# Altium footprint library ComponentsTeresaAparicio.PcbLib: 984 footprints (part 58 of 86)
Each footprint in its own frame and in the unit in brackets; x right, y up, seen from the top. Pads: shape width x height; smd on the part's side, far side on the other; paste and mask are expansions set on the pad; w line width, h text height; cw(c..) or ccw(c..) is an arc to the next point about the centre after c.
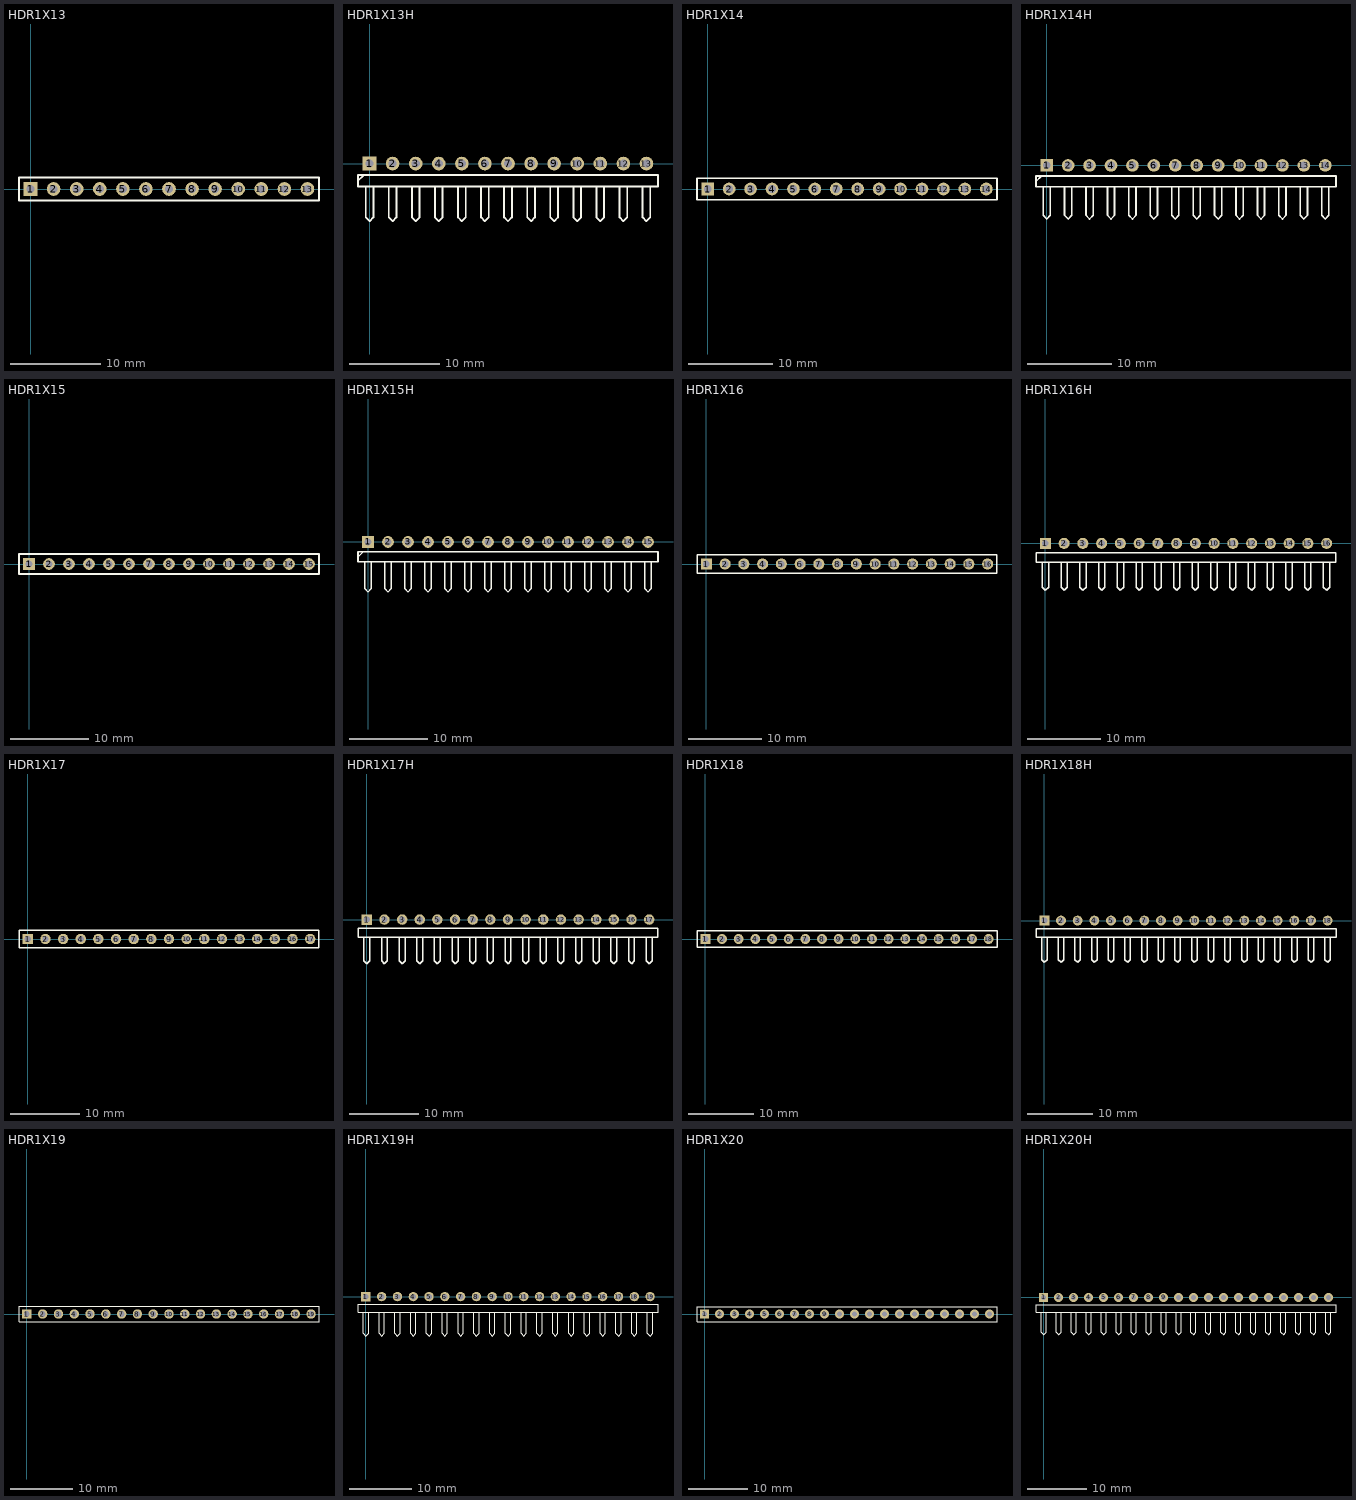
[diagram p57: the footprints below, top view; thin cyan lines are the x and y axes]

## HDR1X13 [mm] "Connector; Header; 13 Position"
pads (13):
  rect 1.5x1.5 hole 0.9: 1(0,0)
  round 1.5 hole 0.9: 2(2.54,0) 3(5.08,0) 4(7.62,0) 5(10.16,0) 6(12.7,0) 7(15.24,0) 8(17.78,0) 9(20.32,0) 10(22.86,0) 11(25.4,0) 12(27.94,0) 13(30.48,0)
Top Overlay:
  lines w0.2: -1.27,-1.27 -1.27,1.27 0.635,1.27 31.75,1.27 31.75,-1.27 -1.27,-1.27

## HDR1X13H [mm] "Connector; Header; 13 Position; Right Angle"
pads (13):
  rect 1.5x1.5 hole 0.9: 1(0,0)
  round 1.5 hole 0.9: 2(2.54,0) 3(5.08,0) 4(7.62,0) 5(10.16,0) 6(12.7,0) 7(15.24,0) 8(17.78,0) 9(20.32,0) 10(22.86,0) 11(25.4,0) 12(27.94,0) 13(30.48,0)
Top Overlay:
  lines w0.2: -1.27,-1.905 -0.635,-1.27 ; -0.423,-2.54 -0.423,-5.927 0,-6.35 0.423,-5.927 0.423,-2.54 ; 2.117,-2.54 2.117,-5.927 2.54,-6.35 2.963,-5.927 2.963,-2.54 ; 4.657,-2.54 4.657,-5.927 5.08,-6.35 5.503,-5.927 5.503,-2.54 ; 7.197,-2.54 7.197,-5.927 7.62,-6.35 8.043,-5.927 8.043,-2.54 ; 9.737,-2.54 9.737,-5.927 10.16,-6.35 10.583,-5.927 10.583,-2.54 ; 12.277,-2.54 12.277,-5.927 12.7,-6.35 13.123,-5.927 13.123,-2.54 ; 14.817,-2.54 14.817,-5.927 15.24,-6.35 15.663,-5.927 15.663,-2.54 ; 17.357,-2.54 17.357,-5.927 17.78,-6.35 18.203,-5.927 18.203,-2.54 ; 19.897,-2.54 19.897,-5.927 20.32,-6.35 20.743,-5.927 20.743,-2.54 ; 22.437,-2.54 22.437,-5.927 22.86,-6.35 23.283,-5.927 23.283,-2.54 ; 24.977,-2.54 24.977,-5.927 25.4,-6.35 25.823,-5.927 25.823,-2.54 ; 27.517,-2.54 27.517,-5.927 27.94,-6.35 28.363,-5.927 28.363,-2.54 ; 30.057,-2.54 30.057,-5.927 30.48,-6.35 30.903,-5.927 30.903,-2.54 ; -1.27,-2.54 31.75,-2.54 31.75,-1.27 0.635,-1.27 -1.27,-1.27 -1.27,-2.54

## HDR1X14 [mm] "Connector; Header; 14 Position"
pads (14):
  rect 1.5x1.5 hole 0.9: 1(0,0)
  round 1.5 hole 0.9: 2(2.54,0) 3(5.08,0) 4(7.62,0) 5(10.16,0) 6(12.7,0) 7(15.24,0) 8(17.78,0) 9(20.32,0) 10(22.86,0) 11(25.4,0) 12(27.94,0) 13(30.48,0) 14(33.02,0)
Top Overlay:
  lines w0.2: -1.27,-1.27 34.29,-1.27 34.29,1.27 0.635,1.27 -1.27,1.27 -1.27,-1.27

## HDR1X14H [mm] "Connector; Header; 14 Position; Right Angle"
pads (14):
  rect 1.5x1.5 hole 0.9: 1(0,0)
  round 1.5 hole 0.9: 2(2.54,0) 3(5.08,0) 4(7.62,0) 5(10.16,0) 6(12.7,0) 7(15.24,0) 8(17.78,0) 9(20.32,0) 10(22.86,0) 11(25.4,0) 12(27.94,0) 13(30.48,0) 14(33.02,0)
Top Overlay:
  lines w0.2: -1.27,-1.905 -0.635,-1.27 ; -0.423,-2.54 -0.423,-5.927 0,-6.35 0.423,-5.927 0.423,-2.54 ; 2.117,-2.54 2.117,-5.927 2.54,-6.35 2.963,-5.927 2.963,-2.54 ; 4.657,-2.54 4.657,-5.927 5.08,-6.35 5.503,-5.927 5.503,-2.54 ; 7.197,-2.54 7.197,-5.927 7.62,-6.35 8.043,-5.927 8.043,-2.54 ; 9.737,-2.54 9.737,-5.927 10.16,-6.35 10.583,-5.927 10.583,-2.54 ; 12.277,-2.54 12.277,-5.927 12.7,-6.35 13.123,-5.927 13.123,-2.54 ; 14.817,-2.54 14.817,-5.927 15.24,-6.35 15.663,-5.927 15.663,-2.54 ; 17.357,-2.54 17.357,-5.927 17.78,-6.35 18.203,-5.927 18.203,-2.54 ; 19.897,-2.54 19.897,-5.927 20.32,-6.35 20.743,-5.927 20.743,-2.54 ; 22.437,-2.54 22.437,-5.927 22.86,-6.35 23.283,-5.927 23.283,-2.54 ; 24.977,-2.54 24.977,-5.927 25.4,-6.35 25.823,-5.927 25.823,-2.54 ; 27.517,-2.54 27.517,-5.927 27.94,-6.35 28.363,-5.927 28.363,-2.54 ; 30.057,-2.54 30.057,-5.927 30.48,-6.35 30.903,-5.927 30.903,-2.54 ; 32.597,-2.54 32.597,-5.927 33.02,-6.35 33.443,-5.927 33.443,-2.54 ; -1.27,-2.54 -1.27,-1.27 0.635,-1.27 34.29,-1.27 34.29,-2.54 -1.27,-2.54

## HDR1X15 [mm] "Connector; Header; 15 Position"
pads (15):
  rect 1.5x1.5 hole 0.9: 1(0,0)
  round 1.5 hole 0.9: 2(2.54,0) 3(5.08,0) 4(7.62,0) 5(10.16,0) 6(12.7,0) 7(15.24,0) 8(17.78,0) 9(20.32,0) 10(22.86,0) 11(25.4,0) 12(27.94,0) 13(30.48,0) 14(33.02,0) 15(35.56,0)
Top Overlay:
  lines w0.2: -1.27,-1.27 -1.27,1.27 0.635,1.27 36.83,1.27 36.83,-1.27 -1.27,-1.27

## HDR1X15H [mm] "Connector; Header; 15 Position; Right Angle"
pads (15):
  rect 1.5x1.5 hole 0.9: 1(0,0)
  round 1.5 hole 0.9: 2(2.54,0) 3(5.08,0) 4(7.62,0) 5(10.16,0) 6(12.7,0) 7(15.24,0) 8(17.78,0) 9(20.32,0) 10(22.86,0) 11(25.4,0) 12(27.94,0) 13(30.48,0) 14(33.02,0) 15(35.56,0)
Top Overlay:
  lines w0.2: -1.27,-1.905 -0.635,-1.27 ; -0.423,-2.54 -0.423,-5.927 0,-6.35 0.423,-5.927 0.423,-2.54 ; 2.117,-2.54 2.117,-5.927 2.54,-6.35 2.963,-5.927 2.963,-2.54 ; 4.657,-2.54 4.657,-5.927 5.08,-6.35 5.503,-5.927 5.503,-2.54 ; 7.197,-2.54 7.197,-5.927 7.62,-6.35 8.043,-5.927 8.043,-2.54 ; 9.737,-2.54 9.737,-5.927 10.16,-6.35 10.583,-5.927 10.583,-2.54 ; 12.277,-2.54 12.277,-5.927 12.7,-6.35 13.123,-5.927 13.123,-2.54 ; 14.817,-2.54 14.817,-5.927 15.24,-6.35 15.663,-5.927 15.663,-2.54 ; 17.357,-2.54 17.357,-5.927 17.78,-6.35 18.203,-5.927 18.203,-2.54 ; 19.897,-2.54 19.897,-5.927 20.32,-6.35 20.743,-5.927 20.743,-2.54 ; 22.437,-2.54 22.437,-5.927 22.86,-6.35 23.283,-5.927 23.283,-2.54 ; 24.977,-2.54 24.977,-5.927 25.4,-6.35 25.823,-5.927 25.823,-2.54 ; 27.517,-2.54 27.517,-5.927 27.94,-6.35 28.363,-5.927 28.363,-2.54 ; 30.057,-2.54 30.057,-5.927 30.48,-6.35 30.903,-5.927 30.903,-2.54 ; 32.597,-2.54 32.597,-5.927 33.02,-6.35 33.443,-5.927 33.443,-2.54 ; 35.137,-2.54 35.137,-5.927 35.56,-6.35 35.983,-5.927 35.983,-2.54 ; -1.27,-2.54 -1.27,-1.27 0.635,-1.27 36.83,-1.27 36.83,-2.54 -1.27,-2.54

## HDR1X16 [mm] "Connector; Header; 16 Position"
pads (16):
  rect 1.5x1.5 hole 0.9: 1(0,0)
  round 1.5 hole 0.9: 2(2.54,0) 3(5.08,0) 4(7.62,0) 5(10.16,0) 6(12.7,0) 7(15.24,0) 8(17.78,0) 9(20.32,0) 10(22.86,0) 11(25.4,0) 12(27.94,0) 13(30.48,0) 14(33.02,0) 15(35.56,0) 16(38.1,0)
Top Overlay:
  lines w0.2: -1.27,-1.27 -1.27,1.27 0.635,1.27 39.37,1.27 39.37,-1.27 -1.27,-1.27

## HDR1X16H [mm] "Connector; Header; 16 Position; Right Angle"
pads (16):
  rect 1.5x1.5 hole 0.9: 1(0,0)
  round 1.5 hole 0.9: 2(2.54,0) 3(5.08,0) 4(7.62,0) 5(10.16,0) 6(12.7,0) 7(15.24,0) 8(17.78,0) 9(20.32,0) 10(22.86,0) 11(25.4,0) 12(27.94,0) 13(30.48,0) 14(33.02,0) 15(35.56,0) 16(38.1,0)
Top Overlay:
  lines w0.2: -0.423,-2.54 -0.423,-5.927 0,-6.35 0.423,-5.927 0.423,-2.54 ; 2.117,-2.54 2.117,-5.927 2.54,-6.35 2.963,-5.927 2.963,-2.54 ; 4.657,-2.54 4.657,-5.927 5.08,-6.35 5.503,-5.927 5.503,-2.54 ; 7.197,-2.54 7.197,-5.927 7.62,-6.35 8.043,-5.927 8.043,-2.54 ; 9.737,-2.54 9.737,-5.927 10.16,-6.35 10.583,-5.927 10.583,-2.54 ; 12.277,-2.54 12.277,-5.927 12.7,-6.35 13.123,-5.927 13.123,-2.54 ; 14.817,-2.54 14.817,-5.927 15.24,-6.35 15.663,-5.927 15.663,-2.54 ; 17.357,-2.54 17.357,-5.927 17.78,-6.35 18.203,-5.927 18.203,-2.54 ; 19.897,-2.54 19.897,-5.927 20.32,-6.35 20.743,-5.927 20.743,-2.54 ; 22.437,-2.54 22.437,-5.927 22.86,-6.35 23.283,-5.927 23.283,-2.54 ; 24.977,-2.54 24.977,-5.927 25.4,-6.35 25.823,-5.927 25.823,-2.54 ; 27.517,-2.54 27.517,-5.927 27.94,-6.35 28.363,-5.927 28.363,-2.54 ; 30.057,-2.54 30.057,-5.927 30.48,-6.35 30.903,-5.927 30.903,-2.54 ; 32.597,-2.54 32.597,-5.927 33.02,-6.35 33.443,-5.927 33.443,-2.54 ; 35.137,-2.54 35.137,-5.927 35.56,-6.35 35.983,-5.927 35.983,-2.54 ; 37.677,-2.54 37.677,-5.927 38.1,-6.35 38.523,-5.927 38.523,-2.54 ; -1.27,-2.54 39.37,-2.54 39.37,-1.27 0.635,-1.27 -1.27,-1.27 -1.27,-2.54

## HDR1X17 [mm] "Connector; Header; 17 Position"
pads (17):
  rect 1.5x1.5 hole 0.9: 1(0,0)
  round 1.5 hole 0.9: 2(2.54,0) 3(5.08,0) 4(7.62,0) 5(10.16,0) 6(12.7,0) 7(15.24,0) 8(17.78,0) 9(20.32,0) 10(22.86,0) 11(25.4,0) 12(27.94,0) 13(30.48,0) 14(33.02,0) 15(35.56,0) 16(38.1,0) 17(40.64,0)
Top Overlay:
  lines w0.2: -1.27,-1.27 41.91,-1.27 41.91,1.27 0.635,1.27 -1.27,1.27 -1.27,-1.27

## HDR1X17H [mm] "Connector; Header; 17 Position; Right Angle"
pads (17):
  rect 1.5x1.5 hole 0.9: 1(0,0)
  round 1.5 hole 0.9: 2(2.54,0) 3(5.08,0) 4(7.62,0) 5(10.16,0) 6(12.7,0) 7(15.24,0) 8(17.78,0) 9(20.32,0) 10(22.86,0) 11(25.4,0) 12(27.94,0) 13(30.48,0) 14(33.02,0) 15(35.56,0) 16(38.1,0) 17(40.64,0)
Top Overlay:
  lines w0.2: -0.423,-2.54 -0.423,-5.927 0,-6.35 0.423,-5.927 0.423,-2.54 ; 2.117,-2.54 2.117,-5.927 2.54,-6.35 2.963,-5.927 2.963,-2.54 ; 4.657,-2.54 4.657,-5.927 5.08,-6.35 5.503,-5.927 5.503,-2.54 ; 7.197,-2.54 7.197,-5.927 7.62,-6.35 8.043,-5.927 8.043,-2.54 ; 9.737,-2.54 9.737,-5.927 10.16,-6.35 10.583,-5.927 10.583,-2.54 ; 12.277,-2.54 12.277,-5.927 12.7,-6.35 13.123,-5.927 13.123,-2.54 ; 14.817,-2.54 14.817,-5.927 15.24,-6.35 15.663,-5.927 15.663,-2.54 ; 17.357,-2.54 17.357,-5.927 17.78,-6.35 18.203,-5.927 18.203,-2.54 ; 19.897,-2.54 19.897,-5.927 20.32,-6.35 20.743,-5.927 20.743,-2.54 ; 22.437,-2.54 22.437,-5.927 22.86,-6.35 23.283,-5.927 23.283,-2.54 ; 24.977,-2.54 24.977,-5.927 25.4,-6.35 25.823,-5.927 25.823,-2.54 ; 27.517,-2.54 27.517,-5.927 27.94,-6.35 28.363,-5.927 28.363,-2.54 ; 30.057,-2.54 30.057,-5.927 30.48,-6.35 30.903,-5.927 30.903,-2.54 ; 32.597,-2.54 32.597,-5.927 33.02,-6.35 33.443,-5.927 33.443,-2.54 ; 35.137,-2.54 35.137,-5.927 35.56,-6.35 35.983,-5.927 35.983,-2.54 ; 37.677,-2.54 37.677,-5.927 38.1,-6.35 38.523,-5.927 38.523,-2.54 ; 40.217,-2.54 40.217,-5.927 40.64,-6.35 41.063,-5.927 41.063,-2.54 ; -1.27,-2.54 41.91,-2.54 41.91,-1.27 0.635,-1.27 -1.27,-1.27 -1.27,-2.54

## HDR1X18 [mm] "Connector; Header; 18 Position"
pads (18):
  rect 1.5x1.5 hole 0.9: 1(0,0)
  round 1.5 hole 0.9: 2(2.54,0) 3(5.08,0) 4(7.62,0) 5(10.16,0) 6(12.7,0) 7(15.24,0) 8(17.78,0) 9(20.32,0) 10(22.86,0) 11(25.4,0) 12(27.94,0) 13(30.48,0) 14(33.02,0) 15(35.56,0) 16(38.1,0) 17(40.64,0) 18(43.18,0)
Top Overlay:
  lines w0.2: -1.27,-1.27 44.45,-1.27 44.45,1.27 0.635,1.27 -1.27,1.27 -1.27,-1.27

## HDR1X18H [mm] "Connector; Header; 18 Position; Right Angle"
pads (18):
  rect 1.5x1.5 hole 0.9: 1(0,0)
  round 1.5 hole 0.9: 2(2.54,0) 3(5.08,0) 4(7.62,0) 5(10.16,0) 6(12.7,0) 7(15.24,0) 8(17.78,0) 9(20.32,0) 10(22.86,0) 11(25.4,0) 12(27.94,0) 13(30.48,0) 14(33.02,0) 15(35.56,0) 16(38.1,0) 17(40.64,0) 18(43.18,0)
Top Overlay:
  lines w0.2: -0.423,-2.54 -0.423,-5.927 0,-6.35 0.423,-5.927 0.423,-2.54 ; 2.117,-2.54 2.117,-5.927 2.54,-6.35 2.963,-5.927 2.963,-2.54 ; 4.657,-2.54 4.657,-5.927 5.08,-6.35 5.503,-5.927 5.503,-2.54 ; 7.197,-2.54 7.197,-5.927 7.62,-6.35 8.043,-5.927 8.043,-2.54 ; 9.737,-2.54 9.737,-5.927 10.16,-6.35 10.583,-5.927 10.583,-2.54 ; 12.277,-2.54 12.277,-5.927 12.7,-6.35 13.123,-5.927 13.123,-2.54 ; 14.817,-2.54 14.817,-5.927 15.24,-6.35 15.663,-5.927 15.663,-2.54 ; 17.357,-2.54 17.357,-5.927 17.78,-6.35 18.203,-5.927 18.203,-2.54 ; 19.897,-2.54 19.897,-5.927 20.32,-6.35 20.743,-5.927 20.743,-2.54 ; 22.437,-2.54 22.437,-5.927 22.86,-6.35 23.283,-5.927 23.283,-2.54 ; 24.977,-2.54 24.977,-5.927 25.4,-6.35 25.823,-5.927 25.823,-2.54 ; 27.517,-2.54 27.517,-5.927 27.94,-6.35 28.363,-5.927 28.363,-2.54 ; 30.057,-2.54 30.057,-5.927 30.48,-6.35 30.903,-5.927 30.903,-2.54 ; 32.597,-2.54 32.597,-5.927 33.02,-6.35 33.443,-5.927 33.443,-2.54 ; 35.137,-2.54 35.137,-5.927 35.56,-6.35 35.983,-5.927 35.983,-2.54 ; 37.677,-2.54 37.677,-5.927 38.1,-6.35 38.523,-5.927 38.523,-2.54 ; 40.217,-2.54 40.217,-5.927 40.64,-6.35 41.063,-5.927 41.063,-2.54 ; 42.757,-2.54 42.757,-5.927 43.18,-6.35 43.603,-5.927 43.603,-2.54 ; -1.27,-2.54 -1.27,-1.27 0.635,-1.27 44.45,-1.27 44.45,-2.54 -1.27,-2.54

## HDR1X19 [mm] "Connector; Header; 19 Position"
pads (19):
  rect 1.5x1.5 hole 0.9: 1(0,0)
  round 1.5 hole 0.9: 2(2.54,0) 3(5.08,0) 4(7.62,0) 5(10.16,0) 6(12.7,0) 7(15.24,0) 8(17.78,0) 9(20.32,0) 10(22.86,0) 11(25.4,0) 12(27.94,0) 13(30.48,0) 14(33.02,0) 15(35.56,0) 16(38.1,0) 17(40.64,0) 18(43.18,0) 19(45.72,0)
Top Overlay:
  lines w0.2: 37.465,1.27 37.677,1.27 ; -1.27,-1.27 -1.27,1.27 0.635,1.27 46.99,1.27 46.99,-1.27 -1.27,-1.27

## HDR1X19H [mm] "Connector; Header; 19 Position; Right Angle"
pads (19):
  rect 1.5x1.5 hole 0.9: 1(0,0)
  round 1.5 hole 0.9: 2(2.54,0) 3(5.08,0) 4(7.62,0) 5(10.16,0) 6(12.7,0) 7(15.24,0) 8(17.78,0) 9(20.32,0) 10(22.86,0) 11(25.4,0) 12(27.94,0) 13(30.48,0) 14(33.02,0) 15(35.56,0) 16(38.1,0) 17(40.64,0) 18(43.18,0) 19(45.72,0)
Top Overlay:
  lines w0.2: -0.423,-2.54 -0.423,-5.927 0,-6.35 0.423,-5.927 0.423,-2.54 ; 2.117,-2.54 2.117,-5.927 2.54,-6.35 2.963,-5.927 2.963,-2.54 ; 4.657,-2.54 4.657,-5.927 5.08,-6.35 5.503,-5.927 5.503,-2.54 ; 7.197,-2.54 7.197,-5.927 7.62,-6.35 8.043,-5.927 8.043,-2.54 ; 9.737,-2.54 9.737,-5.927 10.16,-6.35 10.583,-5.927 10.583,-2.54 ; 12.277,-2.54 12.277,-5.927 12.7,-6.35 13.123,-5.927 13.123,-2.54 ; 14.817,-2.54 14.817,-5.927 15.24,-6.35 15.663,-5.927 15.663,-2.54 ; 17.357,-2.54 17.357,-5.927 17.78,-6.35 18.203,-5.927 18.203,-2.54 ; 19.897,-2.54 19.897,-5.927 20.32,-6.35 20.743,-5.927 20.743,-2.54 ; 22.437,-2.54 22.437,-5.927 22.86,-6.35 23.283,-5.927 23.283,-2.54 ; 24.977,-2.54 24.977,-5.927 25.4,-6.35 25.823,-5.927 25.823,-2.54 ; 27.517,-2.54 27.517,-5.927 27.94,-6.35 28.363,-5.927 28.363,-2.54 ; 30.057,-2.54 30.057,-5.927 30.48,-6.35 30.903,-5.927 30.903,-2.54 ; 32.597,-2.54 32.597,-5.927 33.02,-6.35 33.443,-5.927 33.443,-2.54 ; 35.137,-2.54 35.137,-5.927 35.56,-6.35 35.983,-5.927 35.983,-2.54 ; 37.677,-2.54 37.677,-5.927 38.1,-6.35 38.523,-5.927 38.523,-2.54 ; 40.217,-2.54 40.217,-5.927 40.64,-6.35 41.063,-5.927 41.063,-2.54 ; 42.757,-2.54 42.757,-5.927 43.18,-6.35 43.603,-5.927 43.603,-2.54 ; 45.297,-2.54 45.297,-5.927 45.72,-6.35 46.143,-5.927 46.143,-2.54 ; -1.27,-2.54 -1.27,-1.27 0.635,-1.27 46.99,-1.27 46.99,-2.54 -1.27,-2.54

## HDR1X20 [mm] "Connector; Header; 20 Position"
pads (20):
  rect 1.5x1.5 hole 0.9: 1(0,0)
  round 1.5 hole 0.9: 2(2.54,0) 3(5.08,0) 4(7.62,0) 5(10.16,0) 6(12.7,0) 7(15.24,0) 8(17.78,0) 9(20.32,0) 10(22.86,0) 11(25.4,0) 12(27.94,0) 13(30.48,0) 14(33.02,0) 15(35.56,0) 16(38.1,0) 17(40.64,0) 18(43.18,0) 19(45.72,0) 20(48.26,0)
Top Overlay:
  lines w0.2: -1.27,-1.27 -1.27,1.27 0.635,1.27 49.53,1.27 49.53,-1.27 -1.27,-1.27

## HDR1X20H [mm] "Connector; Header; 20 Position; Right Angle"
pads (20):
  rect 1.5x1.5 hole 0.9: 1(0,0)
  round 1.5 hole 0.9: 2(2.54,0) 3(5.08,0) 4(7.62,0) 5(10.16,0) 6(12.7,0) 7(15.24,0) 8(17.78,0) 9(20.32,0) 10(22.86,0) 11(25.4,0) 12(27.94,0) 13(30.48,0) 14(33.02,0) 15(35.56,0) 16(38.1,0) 17(40.64,0) 18(43.18,0) 19(45.72,0) 20(48.26,0)
Top Overlay:
  lines w0.2: -0.423,-2.54 -0.423,-5.927 0,-6.35 0.423,-5.927 0.423,-2.54 ; 2.117,-2.54 2.117,-5.927 2.54,-6.35 2.963,-5.927 2.963,-2.54 ; 4.657,-2.54 4.657,-5.927 5.08,-6.35 5.503,-5.927 5.503,-2.54 ; 7.197,-2.54 7.197,-5.927 7.62,-6.35 8.043,-5.927 8.043,-2.54 ; 9.737,-2.54 9.737,-5.927 10.16,-6.35 10.583,-5.927 10.583,-2.54 ; 12.277,-2.54 12.277,-5.927 12.7,-6.35 13.123,-5.927 13.123,-2.54 ; 14.817,-2.54 14.817,-5.927 15.24,-6.35 15.663,-5.927 15.663,-2.54 ; 17.357,-2.54 17.357,-5.927 17.78,-6.35 18.203,-5.927 18.203,-2.54 ; 19.897,-2.54 19.897,-5.927 20.32,-6.35 20.743,-5.927 20.743,-2.54 ; 22.437,-2.54 22.437,-5.927 22.86,-6.35 23.283,-5.927 23.283,-2.54 ; 24.977,-2.54 24.977,-5.927 25.4,-6.35 25.823,-5.927 25.823,-2.54 ; 27.517,-2.54 27.517,-5.927 27.94,-6.35 28.363,-5.927 28.363,-2.54 ; 30.057,-2.54 30.057,-5.927 30.48,-6.35 30.903,-5.927 30.903,-2.54 ; 32.597,-2.54 32.597,-5.927 33.02,-6.35 33.443,-5.927 33.443,-2.54 ; 35.137,-2.54 35.137,-5.927 35.56,-6.35 35.983,-5.927 35.983,-2.54 ; 37.677,-2.54 37.677,-5.927 38.1,-6.35 38.523,-5.927 38.523,-2.54 ; 40.217,-2.54 40.217,-5.927 40.64,-6.35 41.063,-5.927 41.063,-2.54 ; 42.757,-2.54 42.757,-5.927 43.18,-6.35 43.603,-5.927 43.603,-2.54 ; 45.297,-2.54 45.297,-5.927 45.72,-6.35 46.143,-5.927 46.143,-2.54 ; 47.837,-2.54 47.837,-5.927 48.26,-6.35 48.683,-5.927 48.683,-2.54 ; -1.27,-2.54 -1.27,-1.27 0.635,-1.27 49.53,-1.27 49.53,-2.54 -1.27,-2.54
